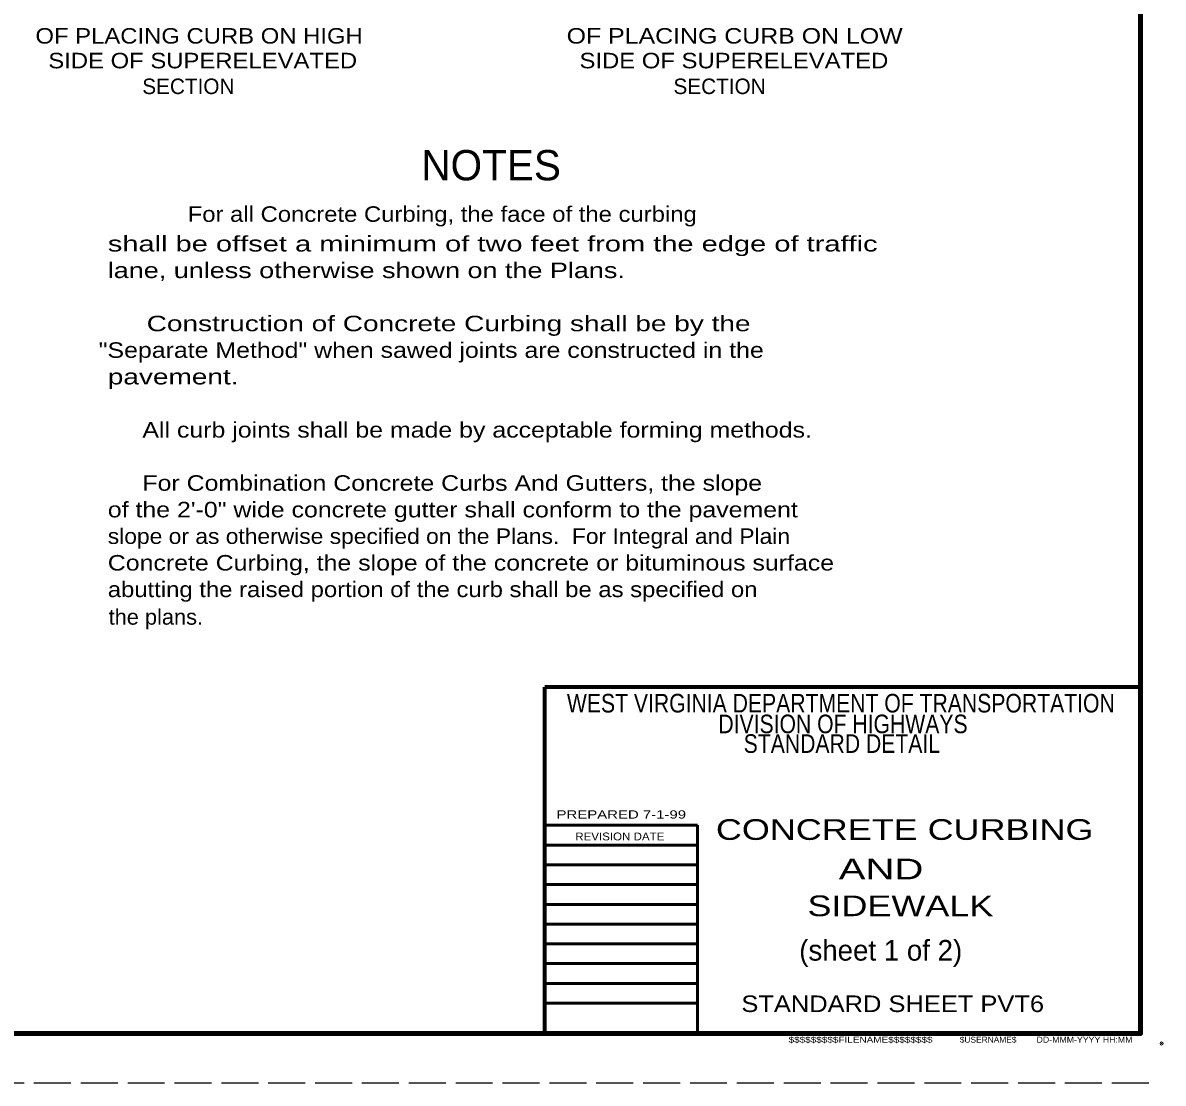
# Model space of a CAD drawing. Extents: x 36.6 to 71.9, y 0.8 to 22.8.
# Drawn here: x 60.45 to 71.93, y 0.78 to 11.46 of the extents above; entities that cross this region are included whole.
import ezdxf
from ezdxf.enums import TextEntityAlignment as Align

# ---------------------------------------------------------------- set-up
doc = ezdxf.new("R2010")
doc.units = 0
doc.header["$LTSCALE"] = 0.062
doc.header["$PDMODE"] = 32
doc.header["$PDSIZE"] = 0.031
doc.linetypes.add('LONG_DASHED', pattern=[7.5, 6, -1.5])
doc.layers.add('1', color=7, linetype='Continuous', lineweight=13)
doc.layers.add('3', color=7, linetype='Continuous', lineweight=25)

msp = doc.modelspace()

# ---------------------------------------------------------------- linework, layer by layer
at = {"layer": '1', "lineweight": 70}
for p in [(71.70225, 4.76825), (65.70225, 1.27842)]:
    msp.add_line(p, (65.70225, 4.76825), dxfattribs=at)
at = {"layer": '1', "lineweight": 53}
for p, q in [((71.70225, 1.27842), (71.70225, 3.77742)), ((67.24017, 3.37742), (65.70225, 3.37742)), ((67.24017, 1.27842), (67.24017, 3.37742)), ((67.24017, 3.17742), (65.70225, 3.17742)), ((67.24017, 2.97842), (65.70225, 2.97842)), ((67.24017, 2.77942), (65.70225, 2.77942)), ((65.70225, 2.68842), (65.70225, 1.27842)), ((67.24017, 2.58042), (65.70225, 2.58042)), ((67.24017, 2.38142), (65.70225, 2.38142)), ((67.24017, 2.18242), (65.70225, 2.18242)), ((67.24017, 1.98342), (65.70225, 1.98342)), ((67.24017, 1.78442), (65.70225, 1.78442)), ((67.24017, 1.58542), (65.70225, 1.58542)), ((71.70225, 1.27842), (65.70225, 1.27842))]:
    msp.add_line(p, q, dxfattribs=at)
at = {"layer": '1', "linetype": 'LONG_DASHED', "lineweight": 25}
msp.add_line((71.78558, 0.77842), (36.58558, 0.77842), dxfattribs=at)
at = {"layer": '1', "lineweight": 158}
msp.add_lwpolyline([(71.70225, 22.27842), (71.70225, 1.27842), (39.20225, 1.27842)], dxfattribs=at)
at = {"layer": '1'}
for p in [(71.70225, 1.27842), (71.91525, 1.17842)]:
    msp.add_point(p, dxfattribs=at)

# ---------------------------------------------------------------- texts
for s, height, width, p in [('WEST VIRGINIA DEPARTMENT OF TRANSPORTATION', 0.1875, 0.85, (68.684, 4.51333)), ('DIVISION OF HIGHWAYS', 0.1875, 0.85, (68.70587, 4.30442)), ('STANDARD DETAIL', 0.1875, 0.85, (68.69458, 4.10625)), (' PREPARED 7-1-99 ', 0.08333, 1.35, (66.47308, 3.44425)), ('    CONCRETE CURBING    ', 0.2083, 1.3, (69.32712, 3.22983)), ('      AND ', 0.2083, 1.45, (68.80904, 2.83217)), ('      SIDEWALK      ', 0.2083, 1.3, (69.28413, 2.46108)), ('STANDARD SHEET PVT6      ', 0.1667, 1.15, (69.42042, 1.4955))]:
    msp.add_text(s, height=height, dxfattribs=dict(at, width=width)).set_placement(p, align=Align.CENTER)
for s, height, width, p in [('REVISION DATE', 0.079, 1.1, (66.00933, 3.22475)), ('$$$$$$$$$FILENAME$$$$$$$$', 0.06, 1.25, (68.158, 1.18667)), ('$USERNAME$', 0.06, 1.05, (69.88208, 1.18667)), ('DD-MMM-YYYY HH:MM', 0.06, 1.1, (70.65567, 1.18667))]:
    msp.add_text(s, height=height, dxfattribs=dict(at, width=width)).set_placement(p)
msp.add_text('     (sheet 1 of 2)     ', height=0.2083, dxfattribs=at).set_placement((69.08571, 2.01333), align=Align.CENTER)
at = {"layer": '3'}
for s, width, p in [('OF PLACING CURB ON HIGH', 1.15, (60.57275, 11.25225)), ('OF PLACING CURB ON LOW', 1.2, (65.92258, 11.25225)), ('SIDE OF SUPERELEVATED', 1.15, (60.70242, 11.00325)), ('SIDE OF SUPERELEVATED', 1.15, (66.05225, 11.00325)), ('For all Concrete Curbing, the face of the curbing', 1.15, (62.10608, 9.45675)), ('shall be offset a minimum of two feet from the edge of traffic', 1.4, (61.30142, 9.15783)), ('lane, unless otherwise shown on the Plans.', 1.3, (61.30142, 8.89)), ('     Construction of Concrete Curbing shall be by the', 1.35, (61.30142, 8.35425)), (' "Separate Method" when sawed joints are constructed in the', 1.2, (61.13975, 8.08633)), ('pavement.', 1.35, (61.30142, 7.8185)), ('     All curb joints shall be made by acceptable forming methods.', 1.2, (61.30142, 7.28283)), ('     For Combination Concrete Curbs And Gutters, the slope', 1.2, (61.30142, 6.74708)), ('of the 2\'-0" wide concrete gutter shall conform to the pavement', 1.2, (61.30142, 6.47925)), ('slope or as otherwise specified on the Plans.  For Integral and Plain', 1.1, (61.30142, 6.21142)), ('Concrete Curbing, the slope of the concrete or bituminous surface', 1.2, (61.30142, 5.9435)), ('abutting the raised portion of the curb shall be as specified on', 1.15, (61.30142, 5.67567)), ('the plans.', 1.05, (61.30975, 5.398))]:
    msp.add_text(s, height=0.1562, dxfattribs=dict(at, width=width)).set_placement(p)
for s, height, p in [('SECTION', 0.1562, (61.64875, 10.74375)), ('SECTION', 0.1562, (66.99858, 10.74375)), ('NOTES', 0.3052, (64.459, 9.87467))]:
    msp.add_text(s, height=height, dxfattribs=at).set_placement(p)

doc.saveas('drawing.dxf')
